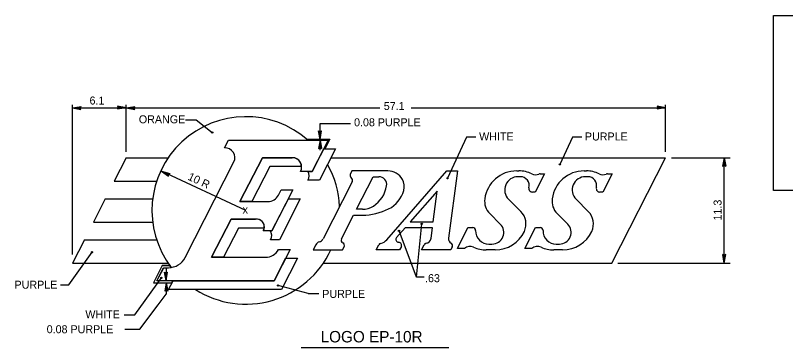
# Model space of a CAD drawing. Extents: x 10268197 to 10269179, y 2141503 to 2142677.
# Drawn here: x 10268648.9 to 10268707, y 2142146.9 to 2142172 of the extents above; entities that cross this region are included whole.
import ezdxf

# ---------------------------------------------------------------- set-up
doc = ezdxf.new("R2010")
doc.units = 0
for name, color, linetype in [('1', 7, 'Continuous'), ('Default', 7, 'Continuous'), ('GSBWFill', 7, 'Continuous'), ('TextAlert', 7, 'Continuous'), ('TextDetails', 7, 'Continuous')]:
    doc.layers.add(name, color=color, linetype=linetype)

msp = doc.modelspace()

# ---------------------------------------------------------------- linework, layer by layer
at = {"layer": '1'}
for p, q in [((10268653.217, 2142153.893), (10268653.217, 2142165.189)), ((10268653.217, 2142164.968), (10268676.419, 2142164.968)), ((10268657.271, 2142161.65), (10268657.271, 2142165.189)), ((10268678.774, 2142164.968), (10268697.974, 2142164.968)), ((10268697.974, 2142161.65), (10268697.974, 2142165.189)), ((10268661.749, 2142164.057), (10268662.549, 2142164.057)), ((10268662.549, 2142164.057), (10268663.77, 2142163.115)), ((10268671.898, 2142163.791), (10268674.205, 2142163.791)), ((10268671.898, 2142162.62), (10268671.898, 2142163.791)), ((10268671.898, 2142161.778), (10268671.898, 2142162.541)), ((10268682.959, 2142162.759), (10268681.519, 2142159.652)), ((10268683.662, 2142162.759), (10268682.959, 2142162.759)), ((10268690.939, 2142162.759), (10268689.986, 2142160.701)), ((10268691.642, 2142162.759), (10268690.939, 2142162.759)), ((10268698.417, 2142161.208), (10268702.841, 2142161.208)), ((10268702.399, 2142153.244), (10268702.399, 2142161.208)), ((10268666.297, 2142157.226), (10268659.944, 2142160.188)), ((10268679.183, 2142152.187), (10268679.569, 2142156.206)), ((10268679.183, 2142152.187), (10268677.855, 2142155.677)), ((10268652.94, 2142151.597), (10268654.697, 2142154.076)), ((10268694.359, 2142153.244), (10268702.841, 2142153.244)), ((10268660.296, 2142152.803), (10268660.296, 2142151.923)), ((10268657.921, 2142149.353), (10268659.928, 2142152.142)), ((10268679.755, 2142152.187), (10268679.183, 2142152.187)), ((10268652.326, 2142151.597), (10268652.94, 2142151.597)), ((10268660.296, 2142151.766), (10268660.296, 2142150.894)), ((10268670.999, 2142150.961), (10268668.727, 2142151.556)), ((10268659.695, 2142150.101), (10268660.296, 2142150.894)), ((10268670.999, 2142150.961), (10268671.8, 2142150.961)), ((10268658.291, 2142148.248), (10268659.695, 2142150.101)), ((10268657.12, 2142149.353), (10268657.921, 2142149.353)), ((10268657.167, 2142148.248), (10268658.291, 2142148.248))]:
    msp.add_line(p, q, dxfattribs=at)
for centre, radius in [((10268663.77, 2142163.114), 0.0442), ((10268689.986, 2142160.7), 0.0442), ((10268681.52, 2142159.651), 0.0442), ((10268679.569, 2142156.206), 0.0518), ((10268677.854, 2142155.676), 0.0518), ((10268654.697, 2142154.075), 0.0442), ((10268659.928, 2142152.141), 0.0442), ((10268668.727, 2142151.555), 0.0442)]:
    msp.add_circle(centre, radius, dxfattribs=at)
at = {"layer": 'Default'}
for p, q in [((10268653.217, 2142164.968), (10268653.864, 2142165.071)), ((10268653.217, 2142164.968), (10268653.837, 2142165.011)), ((10268653.217, 2142164.968), (10268653.86, 2142164.843)), ((10268653.217, 2142164.968), (10268653.835, 2142164.903)), ((10268653.812, 2142164.958), (10268653.864, 2142165.071)), ((10268653.86, 2142164.843), (10268653.812, 2142164.958)), ((10268656.676, 2142164.978), (10268656.624, 2142164.866)), ((10268657.271, 2142164.968), (10268656.624, 2142164.866)), ((10268657.271, 2142164.968), (10268656.628, 2142165.093)), ((10268656.628, 2142165.093), (10268656.676, 2142164.978)), ((10268657.271, 2142164.968), (10268656.652, 2142164.925)), ((10268657.271, 2142164.968), (10268656.653, 2142165.033)), ((10268657.271, 2142164.968), (10268657.918, 2142165.071)), ((10268657.271, 2142164.968), (10268657.891, 2142165.011)), ((10268657.271, 2142164.968), (10268657.914, 2142164.843)), ((10268657.271, 2142164.968), (10268657.889, 2142164.903)), ((10268657.866, 2142164.958), (10268657.918, 2142165.071)), ((10268657.914, 2142164.843), (10268657.866, 2142164.958)), ((10268697.379, 2142164.978), (10268697.328, 2142164.866)), ((10268697.974, 2142164.968), (10268697.328, 2142164.866)), ((10268697.974, 2142164.968), (10268697.331, 2142165.093)), ((10268697.331, 2142165.093), (10268697.379, 2142164.978)), ((10268697.974, 2142164.968), (10268697.355, 2142164.925)), ((10268697.974, 2142164.968), (10268697.356, 2142165.033)), ((10268671.899, 2142162.589), (10268671.774, 2142163.232)), ((10268671.774, 2142163.232), (10268671.889, 2142163.185)), ((10268671.899, 2142162.589), (10268671.834, 2142163.208)), ((10268671.889, 2142163.185), (10268672.002, 2142163.236)), ((10268671.899, 2142162.589), (10268672.002, 2142163.236)), ((10268671.899, 2142162.589), (10268671.943, 2142163.209)), ((10268664.696, 2142161.941), (10268664.997, 2142162.535)), ((10268664.997, 2142162.535), (10268672.519, 2142162.535)), ((10268670.902, 2142162.601), (10268672.627, 2142162.601)), ((10268672.519, 2142162.535), (10268671.314, 2142160.17)), ((10268671.899, 2142162.536), (10268671.774, 2142161.893)), ((10268671.899, 2142162.536), (10268671.834, 2142161.918)), ((10268671.899, 2142162.536), (10268672.002, 2142161.89)), ((10268671.899, 2142162.536), (10268671.943, 2142161.917)), ((10268672.627, 2142162.601), (10268672.255, 2142161.872)), ((10268671.312, 2142160.167), (10268672.181, 2142161.872)), ((10268671.312, 2142160.167), (10268672.181, 2142161.872)), ((10268671.774, 2142161.893), (10268671.889, 2142161.941)), ((10268673.075, 2142161.872), (10268671.869, 2142159.506)), ((10268673.075, 2142161.872), (10268671.869, 2142159.506)), ((10268671.889, 2142161.941), (10268672.002, 2142161.89)), ((10268672.181, 2142161.872), (10268673.075, 2142161.872)), ((10268672.181, 2142161.872), (10268673.075, 2142161.872)), ((10268657.271, 2142161.208), (10268656.37, 2142159.438)), ((10268657.271, 2142161.208), (10268660.444, 2142161.208)), ((10268667.546, 2142161.208), (10268665.856, 2142157.89)), ((10268665.856, 2142157.89), (10268667.546, 2142161.208)), ((10268665.856, 2142157.89), (10268667.546, 2142161.208)), ((10268669.801, 2142161.208), (10268667.546, 2142161.208)), ((10268667.546, 2142161.208), (10268669.801, 2142161.208)), ((10268667.546, 2142161.208), (10268669.801, 2142161.208)), ((10268672.736, 2142161.208), (10268697.974, 2142161.208)), ((10268693.916, 2142153.244), (10268697.974, 2142161.208)), ((10268702.399, 2142161.208), (10268702.274, 2142160.565)), ((10268702.399, 2142161.208), (10268702.334, 2142160.59)), ((10268702.399, 2142161.208), (10268702.501, 2142160.561)), ((10268702.399, 2142161.208), (10268702.442, 2142160.588)), ((10268661.723, 2142153.675), (10268665.395, 2142160.882)), ((10268659.944, 2142160.188), (10268660.573, 2142160.008)), ((10268659.944, 2142160.188), (10268660.474, 2142159.804)), ((10268659.944, 2142160.188), (10268660.476, 2142159.868)), ((10268659.944, 2142160.188), (10268660.523, 2142159.966)), ((10268668.102, 2142160.544), (10268666.749, 2142157.89)), ((10268668.102, 2142160.544), (10268666.749, 2142157.89)), ((10268670.509, 2142160.544), (10268668.102, 2142160.544)), ((10268670.509, 2142160.544), (10268668.102, 2142160.544)), ((10268671.314, 2142160.17), (10268670.429, 2142160.17)), ((10268670.983, 2142160.167), (10268671.312, 2142160.167)), ((10268670.983, 2142160.167), (10268671.312, 2142160.167)), ((10268674.304, 2142160.212), (10268674.184, 2142159.976)), ((10268677.014, 2142160.212), (10268674.304, 2142160.212)), ((10268676.946, 2142155.016), (10268681.464, 2142160.212)), ((10268681.464, 2142160.212), (10268682.26, 2142160.212)), ((10268682.26, 2142160.212), (10268681.598, 2142155.121)), ((10268686.735, 2142160.212), (10268686.903, 2142160.212)), ((10268691.823, 2142160.212), (10268691.991, 2142160.212)), ((10268702.274, 2142160.565), (10268702.388, 2142160.612)), ((10268702.388, 2142160.612), (10268702.501, 2142160.561)), ((10268660.474, 2142159.804), (10268660.479, 2142159.927)), ((10268660.479, 2142159.927), (10268660.573, 2142160.008)), ((10268671.869, 2142159.506), (10268670.984, 2142159.506)), ((10268671.869, 2142159.506), (10268670.984, 2142159.506)), ((10268674.652, 2142157.314), (10268675.903, 2142159.77)), ((10268675.903, 2142159.77), (10268676.33, 2142159.77)), ((10268687.015, 2142159.77), (10268686.826, 2142159.77)), ((10268688.84, 2142159.991), (10268688.136, 2142158.611)), ((10268688.508, 2142159.991), (10268688.84, 2142159.991)), ((10268692.103, 2142159.77), (10268691.913, 2142159.77)), ((10268693.928, 2142159.991), (10268693.225, 2142158.611)), ((10268693.596, 2142159.991), (10268693.928, 2142159.991)), ((10268656.37, 2142159.438), (10268659.572, 2142159.438)), ((10268674.312, 2142159.376), (10268672.121, 2142155.077)), ((10268669.851, 2142158.775), (10268668.273, 2142155.678)), ((10268668.761, 2142158.372), (10268668.966, 2142158.775)), ((10268668.966, 2142158.775), (10268669.851, 2142158.775)), ((10268680.723, 2142158.686), (10268678.703, 2142156.363)), ((10268680.421, 2142156.363), (10268680.723, 2142158.686)), ((10268688.136, 2142158.611), (10268687.915, 2142158.611)), ((10268693.225, 2142158.611), (10268693.003, 2142158.611)), ((10268655.695, 2142158.111), (10268654.794, 2142156.341)), ((10268655.695, 2142158.111), (10268659.273, 2142158.111)), ((10268665.856, 2142157.89), (10268667.973, 2142157.89)), ((10268666.749, 2142157.89), (10268665.856, 2142157.89)), ((10268666.749, 2142157.89), (10268665.856, 2142157.89)), ((10268668.273, 2142155.678), (10268669.513, 2142158.111)), ((10268668.273, 2142155.678), (10268669.513, 2142158.111)), ((10268670.406, 2142158.111), (10268668.828, 2142155.014)), ((10268670.406, 2142158.111), (10268668.828, 2142155.014)), ((10268669.513, 2142158.111), (10268670.406, 2142158.111)), ((10268669.513, 2142158.111), (10268670.406, 2142158.111)), ((10268686.121, 2142158.07), (10268687.049, 2142157.143)), ((10268691.21, 2142158.07), (10268692.137, 2142157.143)), ((10268675.09, 2142157.314), (10268674.652, 2142157.314)), ((10268665.18, 2142156.562), (10268663.715, 2142153.686)), ((10268663.715, 2142153.686), (10268665.18, 2142156.562)), ((10268663.715, 2142153.686), (10268665.18, 2142156.562)), ((10268667.121, 2142156.562), (10268665.18, 2142156.562)), ((10268665.18, 2142156.562), (10268667.038, 2142156.556)), ((10268665.18, 2142156.562), (10268667.038, 2142156.556)), ((10268673.511, 2142155.077), (10268674.426, 2142156.872)), ((10268674.426, 2142156.872), (10268675.09, 2142156.872)), ((10268685.496, 2142156.192), (10268684.701, 2142156.988)), ((10268690.585, 2142156.192), (10268689.789, 2142156.988)), ((10268654.794, 2142156.341), (10268659.273, 2142156.341)), ((10268678.703, 2142156.363), (10268680.421, 2142156.363)), ((10268665.735, 2142155.897), (10268664.608, 2142153.686)), ((10268665.735, 2142155.897), (10268664.608, 2142153.686)), ((10268667.688, 2142155.891), (10268665.735, 2142155.897)), ((10268667.688, 2142155.891), (10268665.735, 2142155.897)), ((10268668.273, 2142155.678), (10268667.606, 2142155.678)), ((10268668.134, 2142155.678), (10268668.273, 2142155.678)), ((10268668.134, 2142155.678), (10268668.273, 2142155.678)), ((10268678.32, 2142155.92), (10268677.678, 2142155.183)), ((10268680.376, 2142155.92), (10268678.32, 2142155.92)), ((10268680.271, 2142155.121), (10268680.376, 2142155.92)), ((10268682.257, 2142154.35), (10268683.06, 2142155.927)), ((10268683.06, 2142155.927), (10268683.416, 2142155.927)), ((10268687.345, 2142154.35), (10268688.148, 2142155.927)), ((10268688.148, 2142155.927), (10268688.504, 2142155.927)), ((10268654.118, 2142155.014), (10268653.217, 2142153.244)), ((10268654.118, 2142155.014), (10268659.572, 2142155.014)), ((10268668.828, 2142155.014), (10268668.165, 2142155.014)), ((10268668.828, 2142155.014), (10268668.165, 2142155.014)), ((10268669.641, 2142154.282), (10268668.436, 2142151.917)), ((10268668.756, 2142154.282), (10268669.641, 2142154.282)), ((10268671.583, 2142154.63), (10268671.385, 2142154.239)), ((10268671.385, 2142154.239), (10268673.597, 2142154.239)), ((10268673.597, 2142154.239), (10268673.717, 2142154.476)), ((10268676.132, 2142154.239), (10268676.324, 2142154.618)), ((10268677.902, 2142154.239), (10268676.132, 2142154.239)), ((10268678.032, 2142154.495), (10268677.902, 2142154.239)), ((10268679.546, 2142154.239), (10268679.742, 2142154.623)), ((10268681.758, 2142154.239), (10268679.546, 2142154.239)), ((10268681.875, 2142154.467), (10268681.758, 2142154.239)), ((10268682.795, 2142154.35), (10268682.257, 2142154.35)), ((10268685.109, 2142154.239), (10268684.443, 2142154.239)), ((10268684.632, 2142154.681), (10268684.871, 2142154.681)), ((10268687.882, 2142154.35), (10268687.345, 2142154.35)), ((10268690.196, 2142154.239), (10268689.531, 2142154.239)), ((10268689.72, 2142154.681), (10268689.958, 2142154.681)), ((10268663.715, 2142153.686), (10268667.775, 2142153.686)), ((10268664.608, 2142153.686), (10268663.715, 2142153.686)), ((10268664.608, 2142153.686), (10268663.715, 2142153.686)), ((10268702.399, 2142153.244), (10268702.296, 2142153.891)), ((10268702.408, 2142153.84), (10268702.296, 2142153.891)), ((10268702.399, 2142153.244), (10268702.355, 2142153.863)), ((10268702.399, 2142153.244), (10268702.523, 2142153.887)), ((10268702.399, 2142153.244), (10268702.463, 2142153.862)), ((10268702.523, 2142153.887), (10268702.408, 2142153.84)), ((10268653.217, 2142153.244), (10268660.444, 2142153.244)), ((10268659.997, 2142153.075), (10268659.332, 2142151.766)), ((10268659.997, 2142153.075), (10268660.562, 2142153.075)), ((10268668.436, 2142151.917), (10268669.303, 2142153.619)), ((10268668.436, 2142151.917), (10268669.303, 2142153.619)), ((10268670.197, 2142153.619), (10268668.992, 2142151.253)), ((10268670.197, 2142153.619), (10268668.992, 2142151.253)), ((10268669.303, 2142153.619), (10268670.197, 2142153.619)), ((10268669.303, 2142153.619), (10268670.197, 2142153.619)), ((10268672.149, 2142153.244), (10268693.916, 2142153.244)), ((10268659.588, 2142151.917), (10268660.09, 2142152.902)), ((10268660.09, 2142152.902), (10268660.461, 2142152.902)), ((10268660.296, 2142151.923), (10268660.17, 2142152.566)), ((10268660.17, 2142152.566), (10268660.285, 2142152.519)), ((10268660.296, 2142151.923), (10268660.231, 2142152.541)), ((10268660.285, 2142152.519), (10268660.398, 2142152.57)), ((10268660.296, 2142151.923), (10268660.398, 2142152.57)), ((10268660.296, 2142151.923), (10268660.339, 2142152.543)), ((10268668.436, 2142151.917), (10268659.588, 2142151.917)), ((10268660.473, 2142151.253), (10268660.811, 2142151.917)), ((10268660.473, 2142151.253), (10268660.811, 2142151.917)), ((10268660.811, 2142151.917), (10268668.436, 2142151.917)), ((10268660.811, 2142151.917), (10268668.436, 2142151.917)), ((10268659.332, 2142151.766), (10268660.719, 2142151.766)), ((10268660.296, 2142151.766), (10268660.193, 2142151.12)), ((10268660.296, 2142151.766), (10268660.252, 2142151.147)), ((10268660.296, 2142151.766), (10268660.42, 2142151.123)), ((10268660.296, 2142151.766), (10268660.36, 2142151.148)), ((10268660.306, 2142151.171), (10268660.193, 2142151.12)), ((10268660.42, 2142151.123), (10268660.306, 2142151.171)), ((10268668.992, 2142151.253), (10268660.473, 2142151.253)), ((10268668.992, 2142151.253), (10268660.473, 2142151.253)), ((10268670.469, 2142146.866), (10268681.618, 2142146.866))]:
    msp.add_line(p, q, dxfattribs=at)
for points in [[(10268670.902, 2142162.601), (10268672.627, 2142162.601), (10268672.255, 2142161.872), (10268672.181, 2142161.872), (10268672.519, 2142162.535), (10268670.979, 2142162.534)], [(10268660.562, 2142153.075), (10268659.997, 2142153.075), (10268659.332, 2142151.766), (10268660.719, 2142151.766), (10268660.811, 2142151.917), (10268659.588, 2142151.917), (10268660.103, 2142152.902), (10268660.466, 2142152.902), (10268660.678, 2142152.918)]]:
    msp.add_lwpolyline(points, close=True, dxfattribs=at)
for centre, radius, start, end in [((10268666.296, 2142157.225), 7.079, 48.59038, 217.4727), ((10268664.744, 2142161.213), 0.73, 332.99985, 93.80449), ((10268669.802, 2142160.499), 0.708, 332.20885, 90), ((10268669.802, 2142160.499), 0.708, 3.58332, 90), ((10268669.802, 2142160.499), 0.708, 3.58332, 90), ((10268666.296, 2142157.225), 7.079, 2.42356, 29.27706), ((10268670.358, 2142159.835), 0.708, 332.20885, 27.91266), ((10268670.358, 2142159.835), 0.708, 332.20885, 27.91266), ((10268677.014, 2142158.951), 1.261, 29.43149, 90), ((10268686.735, 2142157.778), 2.433, 90, 172.30892), ((10268686.903, 2142157.999), 2.212, 64.08957, 90), ((10268691.823, 2142157.778), 2.433, 90, 172.30892), ((10268691.991, 2142157.999), 2.212, 64.08957, 90), ((10268674.38, 2142159.875), 0.221, 152.97842, 231.16017), ((10268674.075, 2142159.496), 0.265, 333.00266, 51.16017), ((10268676.329, 2142159.172), 0.597, 351.07601, 90), ((10268677.148, 2142159.026), 1.106, 344.70738, 29.43149), ((10268686.825, 2142158.774), 0.995, 90, 225), ((10268687.015, 2142159.105), 0.664, 345.69149, 90), ((10268688.159, 2142160.586), 0.664, 244.08957, 292.03474), ((10268688.508, 2142159.725), 0.265, 90, 112.03474), ((10268691.913, 2142158.774), 0.995, 90, 225), ((10268692.103, 2142159.105), 0.664, 345.69149, 90), ((10268693.247, 2142160.586), 0.664, 244.08957, 292.03474), ((10268693.596, 2142159.725), 0.265, 90, 112.03474), ((10268674.734, 2142159.422), 2.212, 302.42062, 351.07601), ((10268687.916, 2142158.876), 0.265, 165.69149, 270), ((10268693.003, 2142158.876), 0.265, 165.69149, 270), ((10268667.973, 2142158.774), 0.885, 270, 332.98829), ((10268676.082, 2142159.318), 2.212, 296.64315, 344.70738), ((10268685.639, 2142157.926), 1.327, 172.30892, 225), ((10268690.727, 2142157.926), 1.327, 172.30892, 225), ((10268675.09, 2142158.862), 1.548, 270, 302.42062), ((10268675.09, 2142161.295), 4.424, 270, 296.64315), ((10268686.11, 2142156.204), 1.327, 334.94996, 45), ((10268691.198, 2142156.204), 1.327, 334.94996, 45), ((10268667.121, 2142155.986), 0.575, 350.35016, 98.33436), ((10268667.121, 2142155.986), 0.575, 350.35016, 98.33436), ((10268667.121, 2142155.986), 0.575, 327.42103, 90), ((10268684.871, 2142155.566), 0.885, 270, 45), ((10268689.958, 2142155.566), 0.885, 270, 45), ((10268667.68, 2142155.323), 0.575, 327.42103, 37.97987), ((10268667.68, 2142155.323), 0.575, 327.42103, 37.97987), ((10268683.416, 2142155.705), 0.221, 358.66645, 90), ((10268684.632, 2142155.677), 0.995, 178.66645, 270), ((10268685.108, 2142156.672), 2.433, 270, 334.94996), ((10268688.504, 2142155.705), 0.221, 358.66645, 90), ((10268689.72, 2142155.677), 0.995, 178.66645, 270), ((10268690.196, 2142156.672), 2.433, 270, 334.94996), ((10268671.977, 2142154.428), 0.442, 106.43168, 152.97425), ((10268671.727, 2142155.277), 0.442, 286.43167, 332.99588), ((10268673.708, 2142154.976), 0.221, 152.98839, 244.78323), ((10268676.278, 2142155.596), 0.885, 282.71621, 318.99659), ((10268677.845, 2142155.037), 0.221, 138.98241, 268.68694), ((10268677.835, 2142154.595), 0.221, 332.97842, 88.68694), ((10268679.832, 2142155.177), 0.442, 279.2397, 352.56317), ((10268681.949, 2142155.074), 0.354, 172.58839, 241.86732), ((10268666.296, 2142157.225), 7.079, 237.53826, 335.04698), ((10268667.775, 2142154.792), 1.106, 270, 332.5096), ((10268673.52, 2142154.576), 0.221, 333.02391, 64.78322), ((10268676.522, 2142154.517), 0.221, 102.71621, 153.02391), ((10268679.939, 2142154.522), 0.221, 99.2397, 153.02391), ((10268681.677, 2142154.567), 0.221, 332.97842, 61.86732), ((10268683.218, 2142153.898), 0.619, 64.37946, 133.18921), ((10268684.443, 2142156.451), 2.212, 244.37946, 270), ((10268688.306, 2142153.898), 0.619, 64.37946, 133.18921), ((10268689.531, 2142156.451), 2.212, 244.37946, 270), ((10268660.461, 2142154.318), 1.416, 270, 332.99913)]:
    msp.add_arc(centre, radius, start, end, dxfattribs=at)
at = {"layer": 'TextAlert'}
msp.add_lwpolyline([(10268706.102, 2142171.951), (10268736.74, 2142171.951), (10268736.74, 2142158.728), (10268706.102, 2142158.728)], close=True, dxfattribs=at)

# ---------------------------------------------------------------- texts
at = {"layer": '1'}
for s, height, p in [('6.1', 0.6037, (10268654.508, 2142165.22)), ('57.1', 0.6037, (10268676.706, 2142164.807)), ('ORANGE', 0.6037, (10268658.227, 2142163.803)), ('0.08 PURPLE', 0.60368, (10268674.465, 2142163.577)), ('WHITE', 0.6037, (10268683.901, 2142162.507)), ('PURPLE', 0.6037, (10268691.881, 2142162.507)), ('x', 0.604, (10268666.056, 2142156.99)), ('PURPLE', 0.6037, (10268648.848, 2142151.314)), ('.63', 0.6037, (10268679.819, 2142151.806)), ('PURPLE', 0.6037, (10268672.067, 2142150.62)), ('WHITE', 0.6037, (10268654.192, 2142149.081)), ('0.08 PURPLE', 0.60368, (10268651.274, 2142147.951))]:
    msp.add_text(s, height=height, dxfattribs=at).set_placement(p)
for s, rotation, p in [('10 R', 334.99906, (10268661.865, 2142159.566)), ('11.3', 90, (10268702.191, 2142156.466))]:
    msp.add_text(s, height=0.6037, rotation=rotation, dxfattribs=at).set_placement(p)
at = {"layer": 'GSBWFill'}
for s, p in [('tableTextHeight:0.0500', (10268690.136, 2142160.996)), ('reportName:OOCEA10', (10268690.136, 2142160.996)), ('plotScale:50', (10268690.137, 2142160.996)), ('letterPositions:2', (10268690.137, 2142160.996)), ('inchesDisplay:0', (10268690.137, 2142160.996))]:
    msp.add_text(s, height=0.000333, dxfattribs=at).set_placement(p)
at = {"layer": 'TextDetails'}
msp.add_text('LOGO EP-10R', height=0.8624, dxfattribs=at).set_placement((10268671.942, 2142147.259))

doc.saveas('drawing.dxf')
